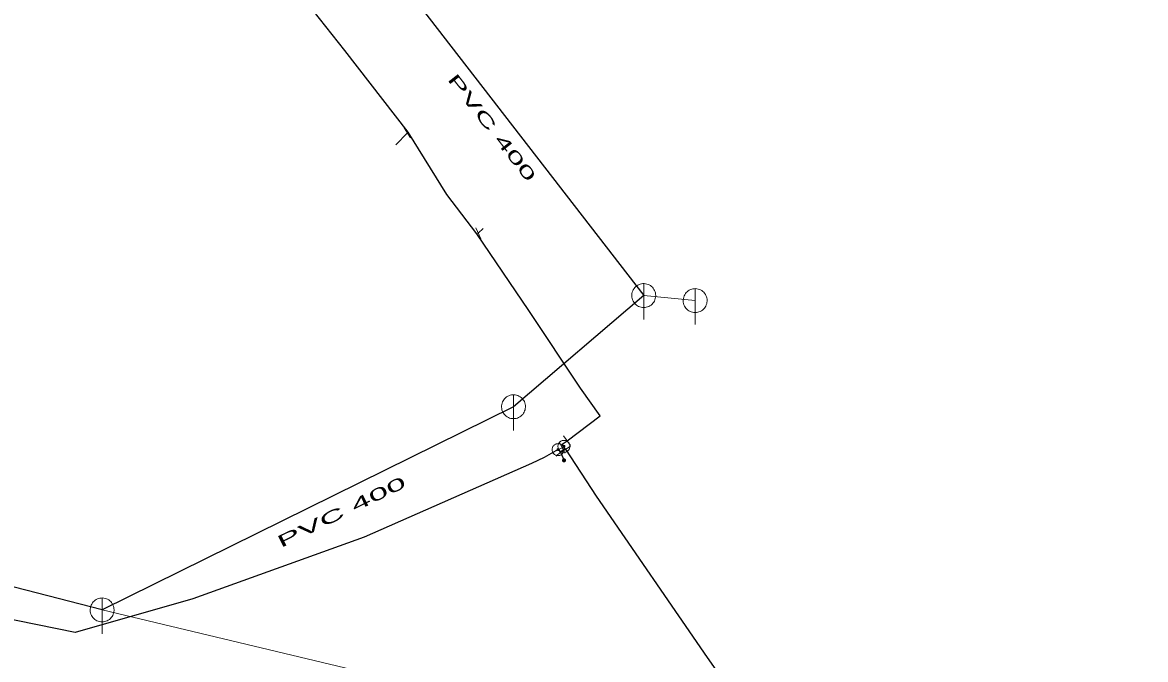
# Model space of a CAD drawing. Extents: x -659250 to -657316, y -997555 to -993684.
# Drawn here: x -658101 to -658007.1, y -996465.3 to -996412 of the extents above; entities that cross this region are included whole.
import ezdxf

# ---------------------------------------------------------------- set-up
doc = ezdxf.new("R2010")
doc.units = 0
doc.header["$LTSCALE"] = 0.4
doc.layers.add('1', color=7, linetype='Continuous')
for name, color, linetype, lineweight in [('11', 7, 'Continuous', 13), ('13', 7, 'Continuous', 13), ('14', 7, 'Continuous', 25), ('17', 7, 'Continuous', 25), ('22', 7, 'Continuous', 13), ('34', 7, 'Continuous', 13), ('47', 7, 'Continuous', 13), ('9', 7, 'Continuous', 13)]:
    doc.layers.add(name, color=color, linetype=linetype, lineweight=lineweight)

msp = doc.modelspace()

# ---------------------------------------------------------------- linework, layer by layer
at = {"layer": '11'}
for p, q in [((-658044.71, -996435.26), (-658049.01, -996434.84)), ((-658068.112, -996467.351), (-658094.3, -996461.12))]:
    msp.add_line(p, q, dxfattribs=at)
at = {"layer": '13'}
for p, q in [((-658068.776, -996421.237), (-658069.748, -996422.25)), ((-658062.844, -996429.629), (-658062.425, -996429.225))]:
    msp.add_line(p, q, dxfattribs=at)
at = {"layer": '14'}
for p, q in [((-658074.53, -996401.82), (-658049.01, -996434.84)), ((-658049.01, -996434.84), (-658059.899, -996444.129))]:
    msp.add_line(p, q, dxfattribs=at)
at = {"layer": '14', "lineweight": 13}
for p, q in [((-658068.699, -996421.191), (-658068.776, -996421.237)), ((-658062.973, -996429.688), (-658062.844, -996429.629)), ((-658056.17, -996447.719), (-658055.833, -996447.556)), ((-658056.17, -996447.719), (-658055.969, -996447.939))]:
    msp.add_line(p, q, dxfattribs=at)
at = {"layer": '14'}
msp.add_lwpolyline([(-658059.899, -996444.129), (-658094.3, -996461.12), (-658148.079, -996447.25)], dxfattribs=at)
at = {"layer": '14', "lineweight": 13}
msp.add_lwpolyline([(-658055.833, -996447.556), (-658055.682, -996447.442), (-658055.539, -996447.693)], dxfattribs=at)
at = {"layer": '17'}
msp.add_line((-658055.969, -996447.939), (-658055.669, -996448.619), dxfattribs=at)
for points in [[(-658055.423, -996446.975), (-658052.642, -996444.888), (-658054.289, -996442.579), (-658058.616, -996436.102), (-658062.973, -996429.688), (-658065.484, -996426.39), (-658068.699, -996421.191), (-658074.013, -996414.35), (-658079.82, -996406.977), (-658086.833, -996398.186), (-658091.995, -996390.978), (-658096.636, -996384.813), (-658099.489, -996380.899)], [(-658055.682, -996447.442), (-658055.824, -996447.274), (-658055.423, -996446.975)], [(-658056.17, -996447.719), (-658057.34, -996448.37), (-658058.399, -996448.87), (-658072.379, -996455.03), (-658086.712, -996460.184), (-658096.55, -996463.013), (-658107.8, -996460.728), (-658119.059, -996456.26), (-658122.789, -996456.213), (-658137.155, -996451.888), (-658147.859, -996448.16), (-658148.32, -996447.94), (-658149.93, -996448.17), (-658151.399, -996448.37), (-658167.629, -996449.05), (-658175.464, -996450.478), (-658185.39, -996452.43), (-658187.329, -996452.923)], [(-658055.539, -996447.693), (-658052.98, -996451.609), (-658043.719, -996465.109), (-658040.35, -996469.87), (-658035.489, -996475.649), (-658026.16, -996487.01), (-658019.39, -996496.739), (-658012.93, -996506.21), (-658008.079, -996513.3), (-658007.05, -996514.899)]]:
    msp.add_lwpolyline(points, dxfattribs=at)
at = {"layer": '22'}
for p, q in [((-658049.01, -996436.84), (-658049.009, -996433.84)), ((-658044.71, -996437.26), (-658044.709, -996434.26)), ((-658059.899, -996446.129), (-658059.898, -996443.129)), ((-658094.3, -996463.12), (-658094.299, -996460.12))]:
    msp.add_line(p, q, dxfattribs=at)
for points in [[(-658048.01, -996434.84), (-658048.015, -996434.731), (-658048.033, -996434.623), (-658048.063, -996434.517), (-658048.103, -996434.416), (-658048.155, -996434.319), (-658048.217, -996434.229), (-658048.289, -996434.146), (-658048.369, -996434.072), (-658048.457, -996434.006), (-658048.551, -996433.951), (-658048.651, -996433.906), (-658048.756, -996433.873), (-658048.863, -996433.851), (-658048.972, -996433.841), (-658049.082, -996433.843), (-658049.19, -996433.857), (-658049.297, -996433.882), (-658049.4, -996433.919), (-658049.498, -996433.968), (-658049.59, -996434.026), (-658049.676, -996434.095), (-658049.753, -996434.172), (-658049.822, -996434.258), (-658049.881, -996434.35), (-658049.929, -996434.448), (-658049.966, -996434.551), (-658049.992, -996434.658), (-658050.006, -996434.766), (-658050.009, -996434.876), (-658049.999, -996434.985), (-658049.978, -996435.092), (-658049.944, -996435.196), (-658049.9, -996435.296), (-658049.845, -996435.391), (-658049.779, -996435.479), (-658049.705, -996435.559), (-658049.622, -996435.631), (-658049.532, -996435.693), (-658049.436, -996435.745), (-658049.334, -996435.786), (-658049.229, -996435.816), (-658049.121, -996435.834), (-658049.011, -996435.84), (-658048.902, -996435.834), (-658048.794, -996435.816), (-658048.689, -996435.787), (-658048.587, -996435.746), (-658048.49, -996435.694), (-658048.4, -996435.632), (-658048.317, -996435.561), (-658048.242, -996435.481), (-658048.177, -996435.393), (-658048.121, -996435.299), (-658048.077, -996435.199), (-658048.043, -996435.095), (-658048.021, -996434.987), (-658048.011, -996434.878)], [(-658043.71, -996435.26), (-658043.715, -996435.151), (-658043.733, -996435.043), (-658043.763, -996434.937), (-658043.803, -996434.836), (-658043.855, -996434.739), (-658043.917, -996434.649), (-658043.989, -996434.566), (-658044.069, -996434.492), (-658044.157, -996434.426), (-658044.251, -996434.371), (-658044.351, -996434.326), (-658044.456, -996434.293), (-658044.563, -996434.271), (-658044.672, -996434.261), (-658044.782, -996434.263), (-658044.89, -996434.277), (-658044.997, -996434.302), (-658045.1, -996434.339), (-658045.198, -996434.388), (-658045.29, -996434.446), (-658045.376, -996434.515), (-658045.453, -996434.592), (-658045.522, -996434.678), (-658045.581, -996434.77), (-658045.629, -996434.868), (-658045.666, -996434.971), (-658045.692, -996435.078), (-658045.706, -996435.186), (-658045.709, -996435.296), (-658045.699, -996435.405), (-658045.678, -996435.512), (-658045.644, -996435.616), (-658045.6, -996435.716), (-658045.545, -996435.811), (-658045.479, -996435.899), (-658045.405, -996435.979), (-658045.322, -996436.051), (-658045.232, -996436.113), (-658045.136, -996436.165), (-658045.034, -996436.206), (-658044.929, -996436.236), (-658044.821, -996436.254), (-658044.711, -996436.26), (-658044.602, -996436.254), (-658044.494, -996436.236), (-658044.389, -996436.207), (-658044.287, -996436.166), (-658044.19, -996436.114), (-658044.1, -996436.052), (-658044.017, -996435.981), (-658043.942, -996435.901), (-658043.877, -996435.813), (-658043.821, -996435.719), (-658043.777, -996435.619), (-658043.743, -996435.515), (-658043.721, -996435.407), (-658043.711, -996435.298)], [(-658058.899, -996444.129), (-658058.904, -996444.02), (-658058.922, -996443.912), (-658058.952, -996443.806), (-658058.992, -996443.705), (-658059.044, -996443.608), (-658059.106, -996443.518), (-658059.178, -996443.435), (-658059.258, -996443.361), (-658059.346, -996443.295), (-658059.44, -996443.24), (-658059.54, -996443.195), (-658059.645, -996443.162), (-658059.752, -996443.14), (-658059.861, -996443.13), (-658059.971, -996443.132), (-658060.079, -996443.146), (-658060.186, -996443.171), (-658060.289, -996443.208), (-658060.387, -996443.257), (-658060.479, -996443.315), (-658060.565, -996443.384), (-658060.642, -996443.461), (-658060.711, -996443.547), (-658060.77, -996443.639), (-658060.818, -996443.737), (-658060.855, -996443.84), (-658060.881, -996443.947), (-658060.895, -996444.055), (-658060.898, -996444.165), (-658060.888, -996444.274), (-658060.867, -996444.381), (-658060.833, -996444.485), (-658060.789, -996444.585), (-658060.734, -996444.68), (-658060.668, -996444.768), (-658060.594, -996444.848), (-658060.511, -996444.92), (-658060.421, -996444.982), (-658060.325, -996445.034), (-658060.223, -996445.075), (-658060.118, -996445.105), (-658060.01, -996445.123), (-658059.9, -996445.129), (-658059.791, -996445.123), (-658059.683, -996445.105), (-658059.578, -996445.076), (-658059.476, -996445.035), (-658059.379, -996444.983), (-658059.289, -996444.921), (-658059.206, -996444.85), (-658059.131, -996444.77), (-658059.066, -996444.682), (-658059.01, -996444.588), (-658058.966, -996444.488), (-658058.932, -996444.384), (-658058.91, -996444.276), (-658058.9, -996444.167)], [(-658093.3, -996461.12), (-658093.305, -996461.011), (-658093.323, -996460.903), (-658093.353, -996460.797), (-658093.393, -996460.696), (-658093.445, -996460.599), (-658093.507, -996460.509), (-658093.579, -996460.426), (-658093.659, -996460.352), (-658093.747, -996460.286), (-658093.841, -996460.231), (-658093.941, -996460.186), (-658094.046, -996460.153), (-658094.153, -996460.131), (-658094.262, -996460.121), (-658094.372, -996460.123), (-658094.48, -996460.137), (-658094.587, -996460.162), (-658094.69, -996460.199), (-658094.788, -996460.248), (-658094.88, -996460.306), (-658094.966, -996460.375), (-658095.043, -996460.452), (-658095.112, -996460.538), (-658095.171, -996460.63), (-658095.219, -996460.728), (-658095.256, -996460.831), (-658095.282, -996460.938), (-658095.296, -996461.046), (-658095.299, -996461.156), (-658095.289, -996461.265), (-658095.268, -996461.372), (-658095.234, -996461.476), (-658095.19, -996461.576), (-658095.135, -996461.671), (-658095.069, -996461.759), (-658094.995, -996461.839), (-658094.912, -996461.911), (-658094.822, -996461.973), (-658094.726, -996462.025), (-658094.624, -996462.066), (-658094.519, -996462.096), (-658094.411, -996462.114), (-658094.301, -996462.12), (-658094.192, -996462.114), (-658094.084, -996462.096), (-658093.979, -996462.067), (-658093.877, -996462.026), (-658093.78, -996461.974), (-658093.69, -996461.912), (-658093.607, -996461.841), (-658093.532, -996461.761), (-658093.467, -996461.673), (-658093.411, -996461.579), (-658093.367, -996461.479), (-658093.333, -996461.375), (-658093.311, -996461.267), (-658093.301, -996461.158)]]:
    msp.add_lwpolyline(points, close=True, dxfattribs=at)
at = {"layer": '34'}
for p, q in [((-658068.521, -996421.667), (-658069.029, -996420.806)), ((-658063.049, -996429.173), (-658062.639, -996430.085)), ((-658056.051, -996447.106), (-658055.615, -996448.006)), ((-658055.723, -996446.575), (-658055.123, -996447.375)), ((-658055.599, -996447.602), (-658056.339, -996448.274)), ((-658055.12, -996447.419), (-658055.957, -996447.966))]:
    msp.add_line(p, q, dxfattribs=at)
at = {"layer": '47'}
for points in [[(-658055.182, -996447.442), (-658055.185, -996447.39), (-658055.193, -996447.338), (-658055.207, -996447.288), (-658055.225, -996447.239), (-658055.249, -996447.192), (-658055.278, -996447.148), (-658055.311, -996447.108), (-658055.348, -996447.071), (-658055.388, -996447.038), (-658055.432, -996447.009), (-658055.479, -996446.985), (-658055.528, -996446.967), (-658055.578, -996446.953), (-658055.63, -996446.945), (-658055.682, -996446.942), (-658055.734, -996446.945), (-658055.786, -996446.953), (-658055.837, -996446.967), (-658055.885, -996446.985), (-658055.932, -996447.009), (-658055.976, -996447.038), (-658056.017, -996447.071), (-658056.054, -996447.108), (-658056.087, -996447.148), (-658056.115, -996447.192), (-658056.139, -996447.239), (-658056.158, -996447.288), (-658056.171, -996447.338), (-658056.179, -996447.39), (-658056.182, -996447.442), (-658056.179, -996447.494), (-658056.171, -996447.546), (-658056.158, -996447.597), (-658056.139, -996447.645), (-658056.115, -996447.692), (-658056.087, -996447.736), (-658056.054, -996447.777), (-658056.017, -996447.814), (-658055.976, -996447.847), (-658055.932, -996447.875), (-658055.885, -996447.899), (-658055.837, -996447.918), (-658055.786, -996447.931), (-658055.734, -996447.939), (-658055.682, -996447.942), (-658055.63, -996447.939), (-658055.578, -996447.931), (-658055.528, -996447.918), (-658055.479, -996447.899), (-658055.432, -996447.875), (-658055.388, -996447.847), (-658055.348, -996447.814), (-658055.311, -996447.777), (-658055.278, -996447.736), (-658055.249, -996447.692), (-658055.225, -996447.645), (-658055.207, -996447.597), (-658055.193, -996447.546), (-658055.185, -996447.494)], [(-658055.67, -996447.72), (-658055.673, -996447.668), (-658055.681, -996447.615), (-658055.695, -996447.566), (-658055.713, -996447.517), (-658055.737, -996447.47), (-658055.766, -996447.426), (-658055.799, -996447.386), (-658055.836, -996447.348), (-658055.876, -996447.316), (-658055.92, -996447.287), (-658055.967, -996447.262), (-658056.016, -996447.245), (-658056.066, -996447.231), (-658056.118, -996447.223), (-658056.17, -996447.22), (-658056.222, -996447.223), (-658056.274, -996447.231), (-658056.325, -996447.245), (-658056.373, -996447.262), (-658056.42, -996447.287), (-658056.464, -996447.316), (-658056.505, -996447.348), (-658056.542, -996447.386), (-658056.575, -996447.426), (-658056.603, -996447.47), (-658056.627, -996447.517), (-658056.646, -996447.566), (-658056.659, -996447.615), (-658056.667, -996447.668), (-658056.67, -996447.72), (-658056.667, -996447.772), (-658056.659, -996447.824), (-658056.646, -996447.875), (-658056.627, -996447.923), (-658056.603, -996447.97), (-658056.575, -996448.014), (-658056.542, -996448.054), (-658056.505, -996448.092), (-658056.464, -996448.125), (-658056.42, -996448.152), (-658056.373, -996448.177), (-658056.325, -996448.196), (-658056.274, -996448.208), (-658056.222, -996448.217), (-658056.17, -996448.22), (-658056.118, -996448.217), (-658056.066, -996448.208), (-658056.016, -996448.196), (-658055.967, -996448.177), (-658055.92, -996448.152), (-658055.876, -996448.125), (-658055.836, -996448.092), (-658055.799, -996448.054), (-658055.766, -996448.014), (-658055.737, -996447.97), (-658055.713, -996447.923), (-658055.695, -996447.875), (-658055.681, -996447.824), (-658055.673, -996447.772)], [(-658056.088, -996447.72), (-658056.088, -996447.711), (-658056.09, -996447.703), (-658056.092, -996447.695), (-658056.095, -996447.686), (-658056.099, -996447.679), (-658056.104, -996447.672), (-658056.109, -996447.664), (-658056.115, -996447.659), (-658056.122, -996447.654), (-658056.129, -996447.649), (-658056.137, -996447.645), (-658056.145, -996447.642), (-658056.153, -996447.64), (-658056.161, -996447.637), (-658056.17, -996447.637), (-658056.179, -996447.637), (-658056.187, -996447.64), (-658056.195, -996447.642), (-658056.203, -996447.645), (-658056.211, -996447.649), (-658056.218, -996447.654), (-658056.225, -996447.659), (-658056.231, -996447.664), (-658056.237, -996447.672), (-658056.241, -996447.679), (-658056.245, -996447.686), (-658056.248, -996447.695), (-658056.25, -996447.703), (-658056.252, -996447.711), (-658056.252, -996447.72), (-658056.252, -996447.728), (-658056.25, -996447.737), (-658056.248, -996447.745), (-658056.245, -996447.753), (-658056.241, -996447.761), (-658056.237, -996447.767), (-658056.231, -996447.775), (-658056.225, -996447.781), (-658056.218, -996447.787), (-658056.211, -996447.791), (-658056.203, -996447.794), (-658056.195, -996447.798), (-658056.187, -996447.799), (-658056.179, -996447.802), (-658056.17, -996447.802), (-658056.161, -996447.802), (-658056.153, -996447.799), (-658056.145, -996447.798), (-658056.137, -996447.794), (-658056.129, -996447.791), (-658056.122, -996447.787), (-658056.115, -996447.781), (-658056.109, -996447.775), (-658056.104, -996447.767), (-658056.099, -996447.761), (-658056.095, -996447.753), (-658056.092, -996447.745), (-658056.09, -996447.737), (-658056.088, -996447.728)], [(-658055.6, -996447.442), (-658055.6, -996447.433), (-658055.602, -996447.425), (-658055.604, -996447.417), (-658055.607, -996447.409), (-658055.611, -996447.401), (-658055.616, -996447.394), (-658055.621, -996447.387), (-658055.627, -996447.381), (-658055.634, -996447.376), (-658055.641, -996447.371), (-658055.649, -996447.367), (-658055.657, -996447.364), (-658055.665, -996447.362), (-658055.673, -996447.36), (-658055.682, -996447.36), (-658055.691, -996447.36), (-658055.699, -996447.362), (-658055.707, -996447.364), (-658055.715, -996447.367), (-658055.723, -996447.371), (-658055.73, -996447.376), (-658055.737, -996447.381), (-658055.743, -996447.387), (-658055.749, -996447.394), (-658055.753, -996447.401), (-658055.757, -996447.409), (-658055.76, -996447.417), (-658055.762, -996447.425), (-658055.764, -996447.433), (-658055.764, -996447.442), (-658055.764, -996447.451), (-658055.762, -996447.459), (-658055.76, -996447.467), (-658055.757, -996447.475), (-658055.753, -996447.483), (-658055.749, -996447.49), (-658055.743, -996447.497), (-658055.737, -996447.503), (-658055.73, -996447.509), (-658055.723, -996447.513), (-658055.715, -996447.517), (-658055.707, -996447.52), (-658055.699, -996447.522), (-658055.691, -996447.524), (-658055.682, -996447.524), (-658055.673, -996447.524), (-658055.665, -996447.522), (-658055.657, -996447.52), (-658055.649, -996447.517), (-658055.641, -996447.513), (-658055.634, -996447.509), (-658055.627, -996447.503), (-658055.621, -996447.497), (-658055.616, -996447.49), (-658055.611, -996447.483), (-658055.607, -996447.475), (-658055.604, -996447.467), (-658055.602, -996447.459), (-658055.6, -996447.451)]]:
    msp.add_lwpolyline(points, close=True, dxfattribs=at)
at = {"layer": '9'}
for points in [[(-658055.795, -996448.619), (-658055.795, -996448.632), (-658055.793, -996448.645), (-658055.79, -996448.658), (-658055.785, -996448.67), (-658055.779, -996448.682), (-658055.772, -996448.693), (-658055.764, -996448.703), (-658055.754, -996448.713), (-658055.744, -996448.721), (-658055.733, -996448.728), (-658055.721, -996448.734), (-658055.709, -996448.739), (-658055.696, -996448.742), (-658055.683, -996448.744), (-658055.67, -996448.746), (-658055.657, -996448.745), (-658055.644, -996448.743), (-658055.631, -996448.74), (-658055.619, -996448.735), (-658055.607, -996448.729), (-658055.596, -996448.722), (-658055.586, -996448.714), (-658055.576, -996448.704), (-658055.568, -996448.694), (-658055.561, -996448.683), (-658055.555, -996448.671), (-658055.55, -996448.659), (-658055.547, -996448.646), (-658055.545, -996448.633), (-658055.543, -996448.62), (-658055.544, -996448.607), (-658055.546, -996448.594), (-658055.549, -996448.581), (-658055.554, -996448.569), (-658055.559, -996448.557), (-658055.567, -996448.546), (-658055.575, -996448.536), (-658055.585, -996448.526), (-658055.595, -996448.518), (-658055.606, -996448.511), (-658055.618, -996448.505), (-658055.63, -996448.5), (-658055.643, -996448.497), (-658055.656, -996448.495), (-658055.669, -996448.494), (-658055.682, -996448.494), (-658055.695, -996448.496), (-658055.708, -996448.499), (-658055.72, -996448.504), (-658055.732, -996448.51), (-658055.743, -996448.517), (-658055.753, -996448.525), (-658055.763, -996448.535), (-658055.771, -996448.545), (-658055.778, -996448.556), (-658055.784, -996448.568), (-658055.789, -996448.58), (-658055.792, -996448.593), (-658055.794, -996448.606)], [(-658055.775, -996448.619), (-658055.776, -996448.63), (-658055.774, -996448.641), (-658055.771, -996448.652), (-658055.767, -996448.662), (-658055.762, -996448.672), (-658055.756, -996448.681), (-658055.749, -996448.69), (-658055.741, -996448.698), (-658055.732, -996448.705), (-658055.723, -996448.711), (-658055.713, -996448.716), (-658055.703, -996448.72), (-658055.692, -996448.723), (-658055.681, -996448.726), (-658055.67, -996448.726), (-658055.659, -996448.726), (-658055.648, -996448.724), (-658055.637, -996448.721), (-658055.627, -996448.717), (-658055.617, -996448.712), (-658055.608, -996448.706), (-658055.599, -996448.699), (-658055.591, -996448.691), (-658055.584, -996448.682), (-658055.578, -996448.673), (-658055.573, -996448.663), (-658055.569, -996448.653), (-658055.566, -996448.642), (-658055.564, -996448.631), (-658055.563, -996448.62), (-658055.563, -996448.609), (-658055.565, -996448.598), (-658055.568, -996448.587), (-658055.572, -996448.577), (-658055.577, -996448.567), (-658055.583, -996448.558), (-658055.59, -996448.549), (-658055.598, -996448.541), (-658055.607, -996448.534), (-658055.616, -996448.528), (-658055.626, -996448.523), (-658055.636, -996448.519), (-658055.647, -996448.516), (-658055.657, -996448.514), (-658055.669, -996448.514), (-658055.68, -996448.513), (-658055.691, -996448.515), (-658055.702, -996448.518), (-658055.712, -996448.522), (-658055.722, -996448.527), (-658055.731, -996448.533), (-658055.74, -996448.54), (-658055.748, -996448.548), (-658055.755, -996448.557), (-658055.761, -996448.566), (-658055.766, -996448.576), (-658055.77, -996448.586), (-658055.773, -996448.597), (-658055.775, -996448.608)], [(-658055.756, -996448.619), (-658055.756, -996448.628), (-658055.755, -996448.637), (-658055.752, -996448.646), (-658055.749, -996448.654), (-658055.745, -996448.662), (-658055.74, -996448.67), (-658055.733, -996448.677), (-658055.728, -996448.683), (-658055.721, -996448.689), (-658055.713, -996448.694), (-658055.705, -996448.698), (-658055.697, -996448.701), (-658055.688, -996448.704), (-658055.679, -996448.705), (-658055.67, -996448.707), (-658055.661, -996448.706), (-658055.652, -996448.705), (-658055.643, -996448.702), (-658055.635, -996448.699), (-658055.627, -996448.695), (-658055.619, -996448.69), (-658055.612, -996448.684), (-658055.606, -996448.678), (-658055.6, -996448.671), (-658055.595, -996448.663), (-658055.591, -996448.655), (-658055.588, -996448.647), (-658055.585, -996448.638), (-658055.584, -996448.629), (-658055.581, -996448.62), (-658055.583, -996448.611), (-658055.584, -996448.602), (-658055.587, -996448.593), (-658055.59, -996448.585), (-658055.594, -996448.577), (-658055.599, -996448.569), (-658055.605, -996448.562), (-658055.611, -996448.556), (-658055.618, -996448.55), (-658055.626, -996448.545), (-658055.634, -996448.541), (-658055.642, -996448.538), (-658055.651, -996448.535), (-658055.66, -996448.534), (-658055.669, -996448.533), (-658055.678, -996448.533), (-658055.687, -996448.534), (-658055.696, -996448.537), (-658055.704, -996448.54), (-658055.712, -996448.544), (-658055.72, -996448.549), (-658055.727, -996448.555), (-658055.733, -996448.561), (-658055.739, -996448.568), (-658055.744, -996448.576), (-658055.748, -996448.584), (-658055.751, -996448.592), (-658055.754, -996448.601), (-658055.755, -996448.61)], [(-658055.736, -996448.619), (-658055.736, -996448.626), (-658055.735, -996448.633), (-658055.733, -996448.64), (-658055.731, -996448.646), (-658055.728, -996448.652), (-658055.724, -996448.658), (-658055.72, -996448.664), (-658055.715, -996448.669), (-658055.709, -996448.673), (-658055.703, -996448.677), (-658055.697, -996448.68), (-658055.691, -996448.683), (-658055.684, -996448.684), (-658055.677, -996448.687), (-658055.67, -996448.687), (-658055.663, -996448.687), (-658055.656, -996448.685), (-658055.649, -996448.684), (-658055.643, -996448.681), (-658055.636, -996448.678), (-658055.631, -996448.674), (-658055.625, -996448.67), (-658055.62, -996448.665), (-658055.616, -996448.659), (-658055.612, -996448.653), (-658055.608, -996448.647), (-658055.606, -996448.641), (-658055.604, -996448.634), (-658055.603, -996448.627), (-658055.602, -996448.62), (-658055.602, -996448.613), (-658055.603, -996448.606), (-658055.605, -996448.599), (-658055.608, -996448.593), (-658055.611, -996448.586), (-658055.615, -996448.581), (-658055.619, -996448.575), (-658055.624, -996448.57), (-658055.63, -996448.566), (-658055.635, -996448.562), (-658055.642, -996448.559), (-658055.648, -996448.556), (-658055.655, -996448.554), (-658055.662, -996448.553), (-658055.669, -996448.553), (-658055.676, -996448.553), (-658055.683, -996448.553), (-658055.69, -996448.555), (-658055.696, -996448.558), (-658055.702, -996448.561), (-658055.708, -996448.565), (-658055.714, -996448.569), (-658055.719, -996448.574), (-658055.723, -996448.58), (-658055.727, -996448.585), (-658055.73, -996448.592), (-658055.733, -996448.598), (-658055.733, -996448.605), (-658055.736, -996448.612)], [(-658055.716, -996448.619), (-658055.716, -996448.624), (-658055.716, -996448.629), (-658055.715, -996448.634), (-658055.713, -996448.638), (-658055.711, -996448.643), (-658055.708, -996448.647), (-658055.705, -996448.65), (-658055.701, -996448.654), (-658055.698, -996448.657), (-658055.694, -996448.66), (-658055.689, -996448.662), (-658055.684, -996448.664), (-658055.68, -996448.665), (-658055.675, -996448.667), (-658055.67, -996448.667), (-658055.665, -996448.667), (-658055.66, -996448.666), (-658055.655, -996448.665), (-658055.651, -996448.663), (-658055.646, -996448.661), (-658055.642, -996448.658), (-658055.638, -996448.655), (-658055.635, -996448.651), (-658055.632, -996448.648), (-658055.629, -996448.644), (-658055.627, -996448.639), (-658055.625, -996448.635), (-658055.624, -996448.63), (-658055.623, -996448.625), (-658055.622, -996448.62), (-658055.622, -996448.615), (-658055.623, -996448.61), (-658055.624, -996448.605), (-658055.626, -996448.601), (-658055.628, -996448.596), (-658055.631, -996448.592), (-658055.634, -996448.588), (-658055.637, -996448.585), (-658055.641, -996448.582), (-658055.645, -996448.579), (-658055.65, -996448.577), (-658055.654, -996448.575), (-658055.659, -996448.574), (-658055.664, -996448.573), (-658055.669, -996448.573), (-658055.674, -996448.573), (-658055.679, -996448.574), (-658055.684, -996448.574), (-658055.688, -996448.576), (-658055.693, -996448.578), (-658055.697, -996448.581), (-658055.7, -996448.584), (-658055.704, -996448.587), (-658055.706, -996448.591), (-658055.71, -996448.595), (-658055.712, -996448.6), (-658055.714, -996448.604), (-658055.715, -996448.609), (-658055.716, -996448.614)], [(-658055.696, -996448.619), (-658055.696, -996448.622), (-658055.697, -996448.625), (-658055.696, -996448.627), (-658055.695, -996448.63), (-658055.694, -996448.633), (-658055.692, -996448.635), (-658055.69, -996448.637), (-658055.688, -996448.639), (-658055.686, -996448.641), (-658055.684, -996448.643), (-658055.681, -996448.645), (-658055.678, -996448.646), (-658055.676, -996448.646), (-658055.673, -996448.647), (-658055.67, -996448.647), (-658055.667, -996448.647), (-658055.664, -996448.647), (-658055.661, -996448.646), (-658055.659, -996448.645), (-658055.656, -996448.644), (-658055.654, -996448.642), (-658055.651, -996448.64), (-658055.649, -996448.638), (-658055.648, -996448.636), (-658055.646, -996448.634), (-658055.645, -996448.631), (-658055.643, -996448.628), (-658055.643, -996448.626), (-658055.642, -996448.623), (-658055.641, -996448.62), (-658055.642, -996448.617), (-658055.642, -996448.614), (-658055.643, -996448.611), (-658055.644, -996448.609), (-658055.645, -996448.606), (-658055.647, -996448.604), (-658055.648, -996448.601), (-658055.65, -996448.599), (-658055.653, -996448.598), (-658055.655, -996448.596), (-658055.657, -996448.595), (-658055.66, -996448.594), (-658055.663, -996448.593), (-658055.666, -996448.593), (-658055.669, -996448.592), (-658055.672, -996448.593), (-658055.675, -996448.592), (-658055.677, -996448.594), (-658055.68, -996448.594), (-658055.683, -996448.595), (-658055.684, -996448.597), (-658055.687, -996448.598), (-658055.689, -996448.6), (-658055.691, -996448.603), (-658055.693, -996448.605), (-658055.694, -996448.608), (-658055.695, -996448.61), (-658055.696, -996448.613), (-658055.696, -996448.616)], [(-658055.677, -996448.619), (-658055.677, -996448.621), (-658055.677, -996448.621), (-658055.676, -996448.621), (-658055.676, -996448.623), (-658055.677, -996448.624), (-658055.675, -996448.624), (-658055.675, -996448.624), (-658055.675, -996448.626), (-658055.675, -996448.626), (-658055.674, -996448.627), (-658055.672, -996448.627), (-658055.672, -996448.627), (-658055.672, -996448.628), (-658055.67, -996448.628), (-658055.67, -996448.628), (-658055.669, -996448.628), (-658055.668, -996448.628), (-658055.668, -996448.627), (-658055.667, -996448.627), (-658055.665, -996448.627), (-658055.665, -996448.626), (-658055.665, -996448.626), (-658055.664, -996448.625), (-658055.664, -996448.625), (-658055.662, -996448.624), (-658055.662, -996448.623), (-658055.661, -996448.622), (-658055.661, -996448.622), (-658055.661, -996448.621), (-658055.661, -996448.62), (-658055.661, -996448.619), (-658055.661, -996448.618), (-658055.661, -996448.618), (-658055.662, -996448.617), (-658055.662, -996448.616), (-658055.663, -996448.615), (-658055.663, -996448.615), (-658055.664, -996448.614), (-658055.664, -996448.614), (-658055.665, -996448.613), (-658055.666, -996448.613), (-658055.667, -996448.612), (-658055.667, -996448.612), (-658055.668, -996448.612), (-658055.669, -996448.612), (-658055.67, -996448.612), (-658055.671, -996448.612), (-658055.671, -996448.612), (-658055.672, -996448.613), (-658055.673, -996448.612), (-658055.674, -996448.614), (-658055.674, -996448.614), (-658055.675, -996448.614), (-658055.675, -996448.614), (-658055.676, -996448.616), (-658055.676, -996448.617), (-658055.676, -996448.618), (-658055.677, -996448.618), (-658055.677, -996448.619)]]:
    msp.add_lwpolyline(points, close=True, dxfattribs=at)

# ---------------------------------------------------------------- texts
at = {"layer": '1'}
for rotation, width, p in [(308, 2.05, (-658065.48, -996416.774)), (26, 2.2, (-658079.358, -996455.954))]:
    msp.add_text('PVC 400 ', height=1, rotation=rotation, dxfattribs=dict(at, width=width)).set_placement(p)

doc.saveas('drawing.dxf')
